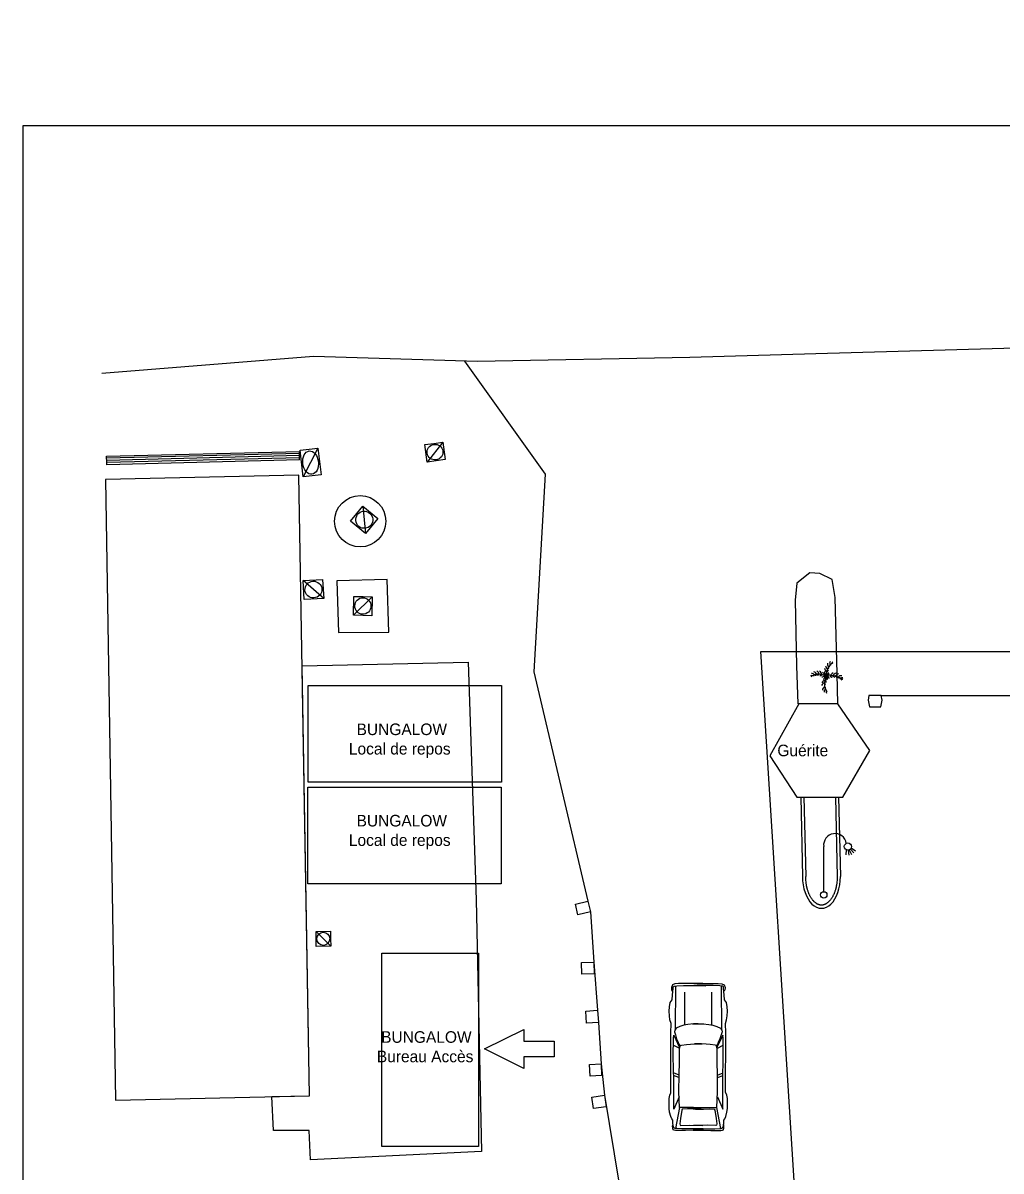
# Model space of a CAD drawing. Extents: x 37864 to 38032, y 453991 to 454052.
# Drawn here: x 37950.43 to 37980.79, y 454015.78 to 454051.41 of the extents above; entities that cross this region are included whole.
import ezdxf

# ---------------------------------------------------------------- set-up
doc = ezdxf.new("R2010")
doc.units = 0
for name, color, linetype in [('DH_TEXTE', 7, 'Continuous'), ('GO MUR EXTERIEUR', 7, 'Continuous'), ('PS_Bolt', 7, 'Continuous'), ('PS_Const', 7, 'Continuous'), ('PS_Dim', 7, 'Continuous'), ('PS_Hidden', 7, 'Continuous'), ('PS_Mid', 7, 'Continuous'), ('PS_Object', 7, 'Continuous'), ('PS_Plate', 7, 'Continuous'), ('PS_RoofWall', 7, 'Continuous'), ('PS_Shape', 7, 'Continuous'), ('PS_Solid', 7, 'Continuous'), ('PS_Weld', 7, 'Continuous'), ('SO_MENUISERIE EXT DOR', 7, 'Continuous'), ('SO_SANITAIRE DETAILLE', 7, 'Continuous')]:
    doc.layers.add(name, color=color, linetype=linetype)

# ---------------------------------------------------------------- blocks, each defined once
blk = doc.blocks.new('V-EP-CANDELAB')
for p, q in [((0, 0.1), (0, 1.5)), ((0.855244, 1.462269), (0.984837, 1.372556)), ((0.700628, 1.399688), (0.684459, 1.240974)), ((0.752708, 1.388229), (0.78082, 1.234594)), ((0.792944, 1.396773), (0.86024, 1.256612)), ((0.830421, 1.422331), (0.931041, 1.303495))]:
    blk.add_line(p, q)
for centre, radius in [((0.75, 1.5), 0.111803), ((0, 0), 0.1)]:
    blk.add_circle(centre, radius)
blk.add_arc((0.35, 1.55), 0.353553, 8.130102, 188.130102)
blk = doc.blocks.new('COCO')
blk.add_line((0.057, -0.022), (0.067, -0.026))
for points in [[(-0.124, 0.143), (-0.094, 0.115), (-0.067, 0.064), (-0.056, 0.038)], [(-0.056, 0.129), (-0.041, 0.09), (-0.035, 0.067)], [(-0.001, 0.067), (0.025, 0.08), (0.054, 0.117)], [(0.089, 0.085), (0.062, 0.069), (0.044, 0.054)], [(-0.088, -0.065), (-0.061, -0.045), (-0.025, -0.027)], [(0.018, -0.083), (0.009, -0.054), (-0.007, -0.023)]]:
    blk.add_lwpolyline(points)
for centre, radius, start, end in [((0.422, 0.078), 0.429, 127.5514, 182.6102), ((0.135, 0.395), 0.11, 162.3561, 228.705), ((0.217, 0.419), 0.124, 153.486, 204.7238), ((0.113, 0.399), 0.033, 254.2928, 325.2228), ((0.228, 0.411), 0.0708, 123.5073, 175.8595), ((0.16, 0.458), 0.0398, 270.4795, 326.1231), ((-0.469, -0.031), 0.0708, 68.8618, 121.214), ((-0.482, 0.051), 0.0398, 278.5982, 334.2418), ((-0.471, -0.017), 0.124, 39.9975, 91.2353), ((-0.251, -0.348), 0.429, 62.3639, 117.1699), ((-0.409, 0.068), 0.033, 279.4985, 350.4285), ((-0.415, 0.047), 0.11, 16.0163, 82.3652), ((-0.35, 0.094), 0.0442, 269.2775, 336.9684), ((-0.363, 0.053), 0.137, 11.6255, 63.3559), ((-0.286, 0.126), 0.0735, 272.4654, 321.7915), ((-0.307, 0.025), 0.171, 13.9387, 59.5235), ((-0.198, 0.112), 0.0737, 255.9805, 321.5114), ((-0.137, 0.118), 0.117, 265.9712, 314.0621), ((-0.069, 0.004), 0.00838, 155.1287, 247.6813), ((-0.035, -0.01), 0.0451, 111.1263, 157.9145), ((-0.067, 0.038), 0.0424, 263.0421, 312.9115), ((0.108, 0.203), 0.18, 192.4617, 204.4421), ((0.108, 0.288), 0.171, 185.1978, 230.7826), ((-0.006, -0.039), 0.0564, 111.1263, 157.9145), ((-0.23, -0.011), 0.18, 14.3805, 16.2304), ((-0.044, 0.06), 0.0105, 68.2237, 160.7763), ((-0.001, 0.06), 0.053, 176.1371, 214.6761), ((-0.054, 0.015), 0.0178, 333.913, 79.7857), ((-0.059, 0.017), 0.0564, 33.1475, 71.0095), ((-0.251, -0.348), 0.429, 54.2202, 60.5021), ((-0.029, 0.043), 0.0223, 247.0081, 352.8808), ((0.107, 0.35), 0.137, 181.3654, 233.0958), ((-0.03, -0.008), 0.0223, 333.913, 79.7857), ((-0.224, -0.046), 0.214, 15.7859, 18.5602), ((0.137, 0.183), 0.214, 225.9092, 228.9354), ((-0.059, 0.017), 0.0564, 24.2214, 26.0625), ((-0.048, 0.174), 0.117, 290.6592, 293.8486), ((0.015, -0.022), 0.0223, 56.5554, 162.4281), ((0.422, 0.078), 0.429, 185.1526, 190.5011), ((-0.066, 0.138), 0.132, 298.2511, 300.0757), ((0.045, 0.01), 0.053, 147.9454, 150.6531), ((0.02, 0.033), 0.0223, 171.6547, 277.5273), ((-0.017, 0.228), 0.0737, 283.2099, 348.7407), ((0.17, -0.394), 0.429, 50.4397, 113.3894), ((0.045, 0.01), 0.053, 100.7837, 124.5304), ((0.036, -0.006), 0.0178, 87.891, 158.5901), ((0.209, -0.093), 0.214, 151.1123, 151.8237), ((-0.012, 0.054), 0.0564, 308.868, 355.6561), ((0.008, 0.312), 0.0735, 282.9298, 332.2559), ((0.034, 0.051), 0.0105, 352.8703, 85.4229), ((0.02, -0.028), 0.0424, 17.0201, 66.8895), ((-0.048, 0.174), 0.117, 331.1939, 338.75), ((0.064, 0.356), 0.0442, 267.7529, 335.4438), ((0.209, -0.093), 0.214, 122.7468, 123.9873), ((0.279, -0.058), 0.192, 112.2412, 152.661), ((0.164, 0.046), 0.058, 195.1268, 282.5722), ((0.322, -0.023), 0.14, 101.8722, 155.687), ((0.302, 0.119), 0.137, 217.8706, 249.7656), ((0.378, -0.017), 0.109, 94.1148, 159.0322), ((0.337, 0.044), 0.0641, 200.3063, 250.058), ((0.447, -0.087), 0.123, 79.7314, 138.9221), ((-0.028, -0.321), 0.14, 105.2055, 159.0203), ((0.013, -0.284), 0.192, 108.2316, 148.6514), ((-0.023, -0.417), 0.11, 109.2993, 175.6482), ((0.059, -0.221), 0.214, 133.3675, 138.1457), ((0.362, -0.23), 0.429, 147.5032, 210.4529), ((-0.165, -0.279), 0.137, 11.127, 43.022), ((-0.049, -0.022), 0.0105, 155.1287, 247.6813), ((-0.074, -0.354), 0.0442, 2.5605, 70.2514), ((-0.046, 0.021), 0.053, 263.0421, 312.9115), ((-0.071, -0.155), 0.058, 338.3203, 65.7657), ((-0.113, -0.103), 0.132, 37.1668, 39.7532), ((0.048, -0.002), 0.0564, 193.7688, 240.5569), ((-0.113, -0.103), 0.132, 3.3838, 8.5978), ((0.026, -0.042), 0.0105, 237.7711, 330.3237), ((-0.016, -0.034), 0.053, 345.6845, 35.5539), ((0.051, 0.021), 0.0451, 249.948, 271.8925), ((0.052, -0.015), 0.00838, 269.1067, 1.6593), ((0.119, 0.095), 0.132, 246.6411, 257.5088), ((0.391, -0.003), 0.0365, 184.8659, 248.5993), ((0.438, -0.048), 0.0241, 163.1519, 234.069), ((0.472, -0.243), 0.21, 80.7993, 105.8694), ((0.452, -0.131), 0.0708, 46.3956, 98.7477), ((0.482, -0.054), 0.0398, 193.3678, 249.0114), ((0.044, -0.469), 0.124, 133.2805, 184.5183), ((-0.044, -0.412), 0.033, 12.7815, 83.7115), ((0.058, -0.467), 0.0708, 162.1448, 214.497), ((-0.023, -0.485), 0.0398, 11.8811, 67.5248)]:
    blk.add_arc(centre, radius, start, end)
blk = doc.blocks.new('A-REGARD')
for p, q in [((0, 1), (1, 1)), ((0, 0), (1, 1)), ((0, 0), (0, 1)), ((1, 1), (1, 0)), ((0.5, 0), (0, 0)), ((1, 0), (0.5, 0))]:
    blk.add_line(p, q)
blk.add_circle((0.5, 0.5), 0.438)
blk = doc.blocks.new('A-GRIL')
for p, q in [((0, 1), (1, 1)), ((0, 1), (0, 0.75)), ((1, 1), (1, 0.75)), ((0, 0.75), (0, 0.5)), ((0, 0.75), (1, 0.75)), ((1, 0.75), (1, 0.5)), ((0, 0.5), (0, 0.25)), ((0, 0.5), (1, 0.5)), ((1, 0.5), (1, 0.25)), ((0, 0.25), (0, 0)), ((0, 0.25), (1, 0.25)), ((1, 0.25), (1, 0)), ((1, 0), (0, 0))]:
    blk.add_line(p, q)
blk = doc.blocks.new('POTO_REC')
at = {"layer": 'PS_Weld'}
for p, q in [((0, 1), (1, 1)), ((0, 0), (0, 1)), ((1, 1), (1, 0)), ((1, 0), (0, 0))]:
    blk.add_line(p, q, dxfattribs=at)
blk = doc.blocks.new('2AUTOT')
at = {"layer": 'PS_Object'}
for points in [[(-2.2848, -0.1314), (-2.2888, 0.4217), (-2.2909, 0.7314), (-2.2836, 0.7814), (-2.2655, 0.8064), (-2.2141, 0.8192), (-2.1613, 0.8262), (-2.1183, 0.817), (-2.0976, 0.8109)], [(-2.2368, -0.1259), (-2.2386, 0.2015), (-2.2354, 0.5377), (-2.2324, 0.697), (-2.2268, 0.7426), (-2.2084, 0.7838), (-2.144, 0.8083), (-2.0432, 0.8164), (-1.9712, 0.8202), (-1.9275, 0.8508), (-1.8518, 0.8827), (-1.7249, 0.9185), (-1.608, 0.9323), (-1.4401, 0.9339), (-1.298, 0.9313), (-1.1945, 0.9113), (-1.1215, 0.8812), (-1.1104, 0.8767), (-0.5447, 0.878), (0.1409, 0.8813), (0.7386, 0.8794), (1.0309, 0.8727), (1.1466, 0.9086), (1.2652, 0.9239), (1.4092, 0.9345), (1.5433, 0.9275), (1.677, 0.9028), (1.7685, 0.8402), (1.9202, 0.833), (2.1132, 0.8123), (2.1691, 0.8089), (2.1877, 0.7793), (2.1974, 0.6996), (2.2046, 0.4901), (2.2064, 0.2453), (2.2048, -0.0084), (2.1947, -0.2029)], [(-2.2271, 0.7235), (-1.5742, 0.6061)], [(-1.2494, 0.6227), (-1.6267, 0.7865), (-0.7381, 0.7926), (0.002, 0.8043), (0.5788, 0.7967), (0.6713, 0.7886), (0.2844, 0.6088)], [(-0.65, 0.6296), (-0.5861, 0.8002)], [(-0.5719, 0.6231), (-0.4967, 0.7965)], [(0.2639, 0.6208), (0.3616, 0.8058)], [(1.007, -0.1403), (1.0182, 0.0307), (1.0193, 0.1767), (1.0035, 0.3523), (0.9788, 0.4823), (0.9395, 0.605), (0.8856, 0.7131), (0.8242, 0.7593), (0.7669, 0.7701), (0.68, 0.7398), (0.5514, 0.701), (0.445, 0.6503), (0.3774, 0.6228), (0.3483, 0.6068), (0.3601, 0.5536), (0.3827, 0.3957), (0.3915, 0.2688), (0.4032, 0.1301), (0.4012, 0.0239), (0.4006, -0.0941)], [(2.1886, 0.7409), (0.8432, 0.7503)], [(2.2747, -0.1136), (2.2724, 0.1046), (2.27, 0.3126), (2.2713, 0.4704), (2.2666, 0.6444), (2.2593, 0.761), (2.2286, 0.8291), (2.1508, 0.8577), (2.0757, 0.8569), (2.0322, 0.8366)], [(-1.6299, -0.0629), (-1.6283, 0.1907), (-1.6233, 0.3735), (-1.6284, 0.5254), (-1.6632, 0.5449), (-1.9214, 0.5809), (-2.084, 0.5999), (-2.1242, 0.5899), (-2.1341, 0.5723), (-2.1215, 0.3067), (-2.1311, -0.1149)], [(-1.5848, -0.2978), (-1.5832, -0.0427), (-1.5806, 0.1815), (-1.5811, 0.4086), (-1.5755, 0.5339), (-1.5821, 0.6091), (-1.0895, 0.6288), (-0.5543, 0.6215), (-0.1709, 0.614), (0.1055, 0.6117), (0.2493, 0.6106), (0.3289, 0.5937), (0.3607, 0.5846)], [(0.9812, 0.4439), (2.0072, 0.4474)], [(-2.2848, 0.1889), (-2.2888, -0.3641), (-2.2909, -0.6738), (-2.2836, -0.7239), (-2.2655, -0.7488), (-2.2141, -0.7617), (-2.1613, -0.7686), (-2.1183, -0.7595), (-2.0976, -0.7534)], [(-2.2368, 0.1834), (-2.2386, -0.144), (-2.2354, -0.4802), (-2.2324, -0.6394), (-2.2268, -0.6851), (-2.2084, -0.7263), (-2.144, -0.7508), (-2.0432, -0.7588), (-1.9712, -0.7627), (-1.9275, -0.7933), (-1.8518, -0.8251), (-1.7249, -0.861), (-1.608, -0.8748), (-1.4401, -0.8764), (-1.298, -0.8738), (-1.1945, -0.8538), (-1.1215, -0.8237), (-1.1104, -0.8192), (-0.5447, -0.8205), (0.1409, -0.8238), (0.7386, -0.8219), (1.0309, -0.8151), (1.1466, -0.8511), (1.2652, -0.8663), (1.4092, -0.877), (1.5433, -0.87), (1.677, -0.8453), (1.7685, -0.7827), (1.9202, -0.7755), (2.1132, -0.7548), (2.1691, -0.7514), (2.1877, -0.7218), (2.1974, -0.642), (2.2046, -0.4326), (2.2064, -0.1878), (2.2048, 0.0659), (2.1947, 0.2605)], [(-1.6299, 0.1205), (-1.6283, -0.1332), (-1.6233, -0.316), (-1.6284, -0.4679), (-1.6632, -0.4874), (-1.9214, -0.5234), (-2.084, -0.5424), (-2.1242, -0.5324), (-2.1341, -0.5148), (-2.1215, -0.2492), (-2.1311, 0.1725)], [(-1.5848, 0.3553), (-1.5832, 0.1002), (-1.5806, -0.1239), (-1.5811, -0.351), (-1.5755, -0.4764), (-1.5821, -0.5516), (-1.0895, -0.5712), (-0.5543, -0.564), (-0.1709, -0.5565), (0.1055, -0.5542), (0.2493, -0.5531), (0.3289, -0.5362), (0.3607, -0.5271)], [(1.007, 0.1978), (1.0182, 0.0268), (1.0193, -0.1192), (1.0035, -0.2948), (0.9788, -0.4248), (0.9395, -0.5475), (0.8856, -0.6556), (0.8242, -0.7018), (0.7669, -0.7126), (0.68, -0.6823), (0.5514, -0.6435), (0.445, -0.5928), (0.3774, -0.5653), (0.3483, -0.5493), (0.3601, -0.4961), (0.3827, -0.3382), (0.3915, -0.2113), (0.4032, -0.0725), (0.4012, 0.0336), (0.4006, 0.1516)], [(2.2747, 0.1711), (2.2724, -0.0471), (2.27, -0.2551), (2.2713, -0.4129), (2.2666, -0.5869), (2.2593, -0.7035), (2.2286, -0.7716), (2.1508, -0.8002), (2.0757, -0.7993), (2.0322, -0.779)], [(-2.2271, -0.666), (-1.5742, -0.5486)], [(-1.2494, -0.5652), (-1.6267, -0.7289), (-0.7381, -0.735), (0.002, -0.7468), (0.5788, -0.7392), (0.6713, -0.731), (0.2844, -0.5513)], [(-0.65, -0.5721), (-0.5861, -0.7427)], [(-0.5719, -0.5656), (-0.4967, -0.739)], [(0.2639, -0.5633), (0.3616, -0.7483)], [(2.1886, -0.6834), (0.8432, -0.6928)], [(0.9812, -0.3864), (2.0072, -0.3899)]]:
    blk.add_lwpolyline(points, dxfattribs=at)
blk = doc.blocks.new('AUTD')
at = {"layer": 'PS_Object'}
blk.add_blockref('2AUTOT', (-2.1886, 0.6834), dxfattribs=at)

msp = doc.modelspace()

# ---------------------------------------------------------------- linework, layer by layer
at = {"layer": 'DEFPOINTS'}
msp.add_lwpolyline([(37950.431, 453990.816), (38032.431, 453990.816), (38032.431, 454048.216), (37950.431, 454048.216)], close=True, dxfattribs=at)
at = {"layer": 'GO MUR EXTERIEUR'}
msp.add_lwpolyline([(37953.302, 454017.981), (37959.327, 454018.115), (37958.989, 454037.373), (37952.995, 454037.241)], close=True, dxfattribs=at)
at = {"layer": 'PS_Dim'}
msp.add_line((37977.069, 454030.534), (37983.015, 454030.534), dxfattribs=at)
at = {"layer": 'PS_Hidden'}
msp.add_line((37975.043, 454004.703), (37973.328, 454031.906), dxfattribs=at)
msp.add_lwpolyline([(37973.328, 454031.906), (37986.869, 454031.906), (37986.869, 454022.877), (37991.287, 454022.877)], dxfattribs=at)
for points in [[(37959.28, 454027.854), (37959.28, 454030.854), (37965.28, 454030.854), (37965.28, 454027.854)], [(37959.273, 454024.69), (37959.273, 454027.69), (37965.273, 454027.69), (37965.273, 454024.69)], [(37961.565, 454022.546), (37964.565, 454022.546), (37964.565, 454016.546), (37961.565, 454016.546)], [(37964.757, 454019.568), (37965.972, 454020.176), (37965.972, 454019.81), (37966.914, 454019.81), (37966.914, 454019.327), (37965.972, 454019.327), (37965.972, 454018.961)]]:
    msp.add_lwpolyline(points, close=True, dxfattribs=at)
at = {"layer": 'PS_Mid'}
for points in [[(37960.174, 454034.093), (37960.224, 454032.494), (37961.785, 454032.502), (37961.733, 454034.143), (37960.174, 454034.093)], [(37958.158, 454018.089), (37959.327, 454018.115), (37959.093, 454031.459), (37964.245, 454031.57), (37964.495, 454024.196), (37964.659, 454016.382), (37959.352, 454016.131), (37959.315, 454017.038), (37958.203, 454017.039), (37958.158, 454018.089)]]:
    msp.add_lwpolyline(points, dxfattribs=at)
msp.add_circle((37960.898, 454035.947), 0.795, dxfattribs=at)
at = {"layer": 'PS_Plate'}
msp.add_lwpolyline([(37976.689, 454030.534), (37976.665, 454030.398), (37976.701, 454030.185), (37977.054, 454030.19), (37977.096, 454030.398), (37977.069, 454030.534), (37976.689, 454030.534)], dxfattribs=at)
at = {"layer": 'PS_Shape'}
msp.add_line((37975.748, 454027.388), (37975.804, 454024.917), dxfattribs=at)
at = {"layer": 'PS_Solid'}
for points in [[(37953.302, 454017.981), (37959.327, 454018.115), (37958.989, 454037.373), (37952.995, 454037.241)], [(37974.51, 454030.285), (37973.615, 454028.666), (37974.454, 454027.388), (37975.878, 454027.388), (37976.719, 454028.831), (37975.72, 454030.285), (37974.51, 454030.285)]]:
    msp.add_lwpolyline(points, dxfattribs=at)
at = {"layer": 'SO_SANITAIRE DETAILLE'}
for p, q in [((37974.572, 454027.388), (37974.628, 454024.917)), ((37974.672, 454027.39), (37974.728, 454024.919)), ((37975.648, 454027.385), (37975.704, 454024.914)), ((37975.748, 454027.388), (37975.804, 454024.917))]:
    msp.add_line(p, q, dxfattribs=at)
for points in [[(38017.828, 454051.412), (38017.827, 454048.283), (38017.43, 454042.806), (38015.386, 454042.628), (38010.805, 454042.4), (38005.064, 454042.102), (37999.448, 454041.936), (37993.784, 454041.715), (37987.562, 454041.497), (37981.968, 454041.336), (37975.041, 454041.141), (37971.132, 454041.024), (37964.54, 454040.907), (37959.445, 454041.057), (37952.881, 454040.532)], [(37964.134, 454040.919), (37966.644, 454037.408), (37966.288, 454031.271), (37967.968, 454024.153), (37967.968, 454024.153), (37967.968, 454024.153), (37968.041, 454023.821), (37968.148, 454022.267), (37968.267, 454020.769), (37968.293, 454020.39), (37968.375, 454019.105), (37968.48, 454018.134), (37968.928, 454015.43), (37969.023, 454013.593), (37968.943, 454012.12), (37968.959, 454010.925), (37969.152, 454009.367), (37969.326, 454007.587), (37969.351, 454004.477)], [(37975.719, 454030.285), (37975.7, 454031.215), (37975.635, 454033.583), (37975.547, 454034.136), (37975.164, 454034.328), (37974.855, 454034.343), (37974.448, 454034.029), (37974.402, 454033.494), (37974.445, 454031.462), (37974.483, 454030.285)]]:
    msp.add_lwpolyline(points, dxfattribs=at)
msp.add_ellipse((37975.215, 454024.917), major_axis=(0, 0.983), ratio=0.599267, start_param=1.570796, end_param=4.712389, dxfattribs=at)
msp.add_open_spline([(37975.704, 454024.917), (37975.704, 454024.855), (37975.701, 454024.795), (37975.69, 454024.706), (37975.686, 454024.677), (37975.675, 454024.62), (37975.669, 454024.592), (37975.655, 454024.537), (37975.648, 454024.51), (37975.631, 454024.458), (37975.622, 454024.433), (37975.603, 454024.384), (37975.592, 454024.36), (37975.57, 454024.315), (37975.558, 454024.294), (37975.534, 454024.252), (37975.521, 454024.233), (37975.495, 454024.197), (37975.481, 454024.181), (37975.454, 454024.151), (37975.44, 454024.137), (37975.412, 454024.112), (37975.398, 454024.101), (37975.37, 454024.081), (37975.355, 454024.073), (37975.334, 454024.062), (37975.327, 454024.059), (37975.313, 454024.053), (37975.306, 454024.05), (37975.292, 454024.045), (37975.285, 454024.043), (37975.271, 454024.04), (37975.264, 454024.038), (37975.25, 454024.036), (37975.243, 454024.035), (37975.229, 454024.034), (37975.222, 454024.034), (37975.208, 454024.034), (37975.201, 454024.034), (37975.187, 454024.035), (37975.18, 454024.036), (37975.166, 454024.038), (37975.159, 454024.04), (37975.145, 454024.043), (37975.138, 454024.045), (37975.124, 454024.05), (37975.117, 454024.053), (37975.103, 454024.059), (37975.096, 454024.062), (37975.075, 454024.073), (37975.061, 454024.081), (37975.033, 454024.101), (37975.018, 454024.112), (37974.99, 454024.137), (37974.976, 454024.151), (37974.949, 454024.181), (37974.936, 454024.197), (37974.91, 454024.233), (37974.897, 454024.252), (37974.872, 454024.294), (37974.86, 454024.315), (37974.838, 454024.36), (37974.828, 454024.384), (37974.808, 454024.433), (37974.799, 454024.458), (37974.783, 454024.51), (37974.775, 454024.537), (37974.761, 454024.592), (37974.755, 454024.62), (37974.745, 454024.677), (37974.74, 454024.706), (37974.73, 454024.795), (37974.726, 454024.855), (37974.726, 454024.917)], degree=3, dxfattribs=at)

# ---------------------------------------------------------------- block references
at = {"layer": 'DH_TEXTE'}
for p, xscale, yscale, rotation in [((37960.981, 454036.418), 0.6054364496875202, 0.6060132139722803, -129.34230381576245), ((37961.272, 454033.603), 0.5701535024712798, 0.5871244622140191, 178.66057200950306), ((37959.983, 454022.757), 0.46789552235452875, 0.451478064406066, 90.67418991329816)]:
    msp.add_blockref('A-REGARD', p, dxfattribs=dict(at, xscale=xscale, yscale=yscale, rotation=rotation))
at = {"layer": 'PS_Bolt'}
for p, xscale, yscale, rotation in [((37967.968, 454024.153), 0.4, 0.3400000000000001, -167.44146717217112), ((37968.148, 454022.267), 0.3800000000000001, 0.37, -178.2062050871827), ((37968.267, 454020.769), 0.37000000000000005, 0.38, -176.09201026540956), ((37968.375, 454019.105), 0.3599999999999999, 0.35999999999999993, -177.5289290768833), ((37968.48, 454018.134), 0.4000000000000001, 0.3599999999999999, -171.57385078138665)]:
    msp.add_blockref('POTO_REC', p, dxfattribs=dict(at, xscale=xscale, yscale=yscale, rotation=rotation))
at = {"layer": 'PS_Const', "rotation": 2.2526485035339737e-05}
msp.add_blockref('COCO', (37975.375, 454031.118), dxfattribs=at)
at = {"layer": 'PS_Hidden', "rotation": 89.99999999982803}
msp.add_blockref('AUTD', (37972.104, 454021.518), dxfattribs=at)
at = {"layer": 'PS_RoofWall', "rotation": 2.2526485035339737e-05}
msp.add_blockref('V-EP-CANDELAB', (37975.286, 454024.35), dxfattribs=at)
at = {"layer": 'SO_MENUISERIE EXT DOR'}
for name, p, xscale, yscale, rotation in [('A-REGARD', (37963.461, 454038.405), 0.5669079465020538, 0.5505522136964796, -171.88689627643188), ('A-GRIL', (37959.011, 454038.116), 5.986300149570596, 0.266026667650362, -178.57759171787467), ('A-REGARD', (37959.588, 454038.212), 0.5576843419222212, 0.8307691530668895, -173.43745525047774), ('A-REGARD', (37959.764, 454033.548), 0.5916208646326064, 0.6026969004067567, 93.16261782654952)]:
    msp.add_blockref(name, p, dxfattribs=dict(at, xscale=xscale, yscale=yscale, rotation=rotation))

# ---------------------------------------------------------------- texts
at = {"layer": 'PS_Hidden'}
for s, p in [('BUNGALOW', (37960.785, 454029.31)), ('Local de repos', (37960.546, 454028.707)), ('Guérite', (37973.846, 454028.653)), ('BUNGALOW', (37960.785, 454026.474)), ('Local de repos', (37960.546, 454025.871)), ('BUNGALOW', (37961.548, 454019.76)), ('Bureau Accès', (37961.415, 454019.157))]:
    msp.add_text(s, height=0.36, rotation=360, dxfattribs=at).set_placement(p)

doc.saveas('drawing.dxf')
